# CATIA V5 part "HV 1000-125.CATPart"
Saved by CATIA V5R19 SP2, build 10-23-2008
Part number: HV 1000-125
Bounding box of the stored display mesh (mm): x -24.865 to 24.865, y -24.997 to 24.997, z 0 to 307
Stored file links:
  C:\Users\Bora\Desktop\3D KATI MODEL- CATIA PART\HV serisi\HV 1000\HV 1000-125.CATPart
  C:\Program Files\Dassault Systemes\B19\intel_a\reffiles\standard\MetricThickPitch.txt
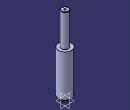
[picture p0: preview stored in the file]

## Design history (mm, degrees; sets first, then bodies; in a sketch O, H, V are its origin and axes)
Body1 (main body)
  Sketch1 on yz-plane, origin (0, 0, 0), H (0, 1, 0), V (0, 0, 1)
    point P1 (14, 305)
    point P3 (14, 305)
    point P8 (8, 17)
    point P10 (8, 1)
    point P11 (8, 17)
    point P12 (8, 1)
    arc A1 centre (12, 305) radius 2 from (14, 305) to (12, 307) ccw
    line L1 (14, 305) -> (14, 181)
    arc A2 centre (8, 18) radius 1 from (8, 19) to (8, 17) ccw
    line L2 (7, 0) -> (8, 1)
    line L3 (8, 17) -> (8, 1)
    line L4 (0, 0) -> (7, 0)
    line L5 (8, 19) -> (25, 19)
    line L6 (14, 181) -> (25, 181)
    line L7 (12, 307) -> (0, 307)
    point P13 (0, 307)
    line L8 (25, 181) -> (25, 19)
    horizontal: L4 H, L6 H
    tangency: L5 A2, L7 A1
    coincidence: P13 V, P1 P3, P8 P11, P10 P12
    vertical: L8 V
  Shaft1: profile Sketch1, axis Sketch1.V, angle 360
  Sketch2 on face of Shaft1 from Sketch1.L4, origin (0, 0, 0), H (1, 0, 0), V (0, -1, 0)
    point P1 (0, 0)
  Hole1: placed by Sketch2, at (0, 0, 0) direction (0, 0, 1), diameter 13.835, depth 19, threaded "M16", thread diameter 16, thread depth 19, pitch 2
  Sketch3 on face of Shaft1 from Sketch1.L7, origin (0, 0, 307), H (1, 0, 0), V (0, 1, 0)
    point P1 (0, 0)
  Hole2: placed by Sketch3, at (0, 0, 307) direction (0, 0, -1), diameter 6.647, depth 15, threaded "M8", thread diameter 8, thread depth 15, pitch 1.25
